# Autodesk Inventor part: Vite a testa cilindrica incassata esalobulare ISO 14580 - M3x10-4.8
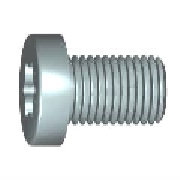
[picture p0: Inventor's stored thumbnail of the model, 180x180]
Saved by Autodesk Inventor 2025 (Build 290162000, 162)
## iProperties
Created: 2024-01
Part Number: Vite a testa cilindrica incassata esalobulare ISO 14580 - M3x10-4.8
Material: Acciaio
Description: ISO 14580 - Viti a testa cilindrica incassata esalobulare - Seconda edizione
Document SubType Name: Modeling
Standard: 14580
Designer: Ryzen5700u
Standards Organization: ISO
Language: it-IT
Size Designation: M3x10-4.8
Categories: <MemberInstance><Categories><Category DisplayName="Elementi di fissaggio" InternalName="e4da775c-781d-43d5-af7c-5136215cf5a6" Mnemonic="FSTN"><Category DisplayN
Density: 7.85 g/cm^3
Appearance: Lamiera
IsCustomPart: 0
Author: Ryzen5700u
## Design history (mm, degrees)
revolve "Revolution1" stored, may be unused: angle "d4" = 90 deg
thread "Thread1" dims "d6" = 10 (= b), "d7" = 0
sketch "Sketch2" dims "d21" = 2.8 (= A_)
  geometry: L1 (-0.849, -0.49)-(-1.4, 0); L2 (0, 0)-(-0.849, -0.49); L3 (0, 0)-(-0.849, 0.49); L4 (-4.144, 0)-(4.144, 0) reference; L5 (-1.4, 0)-(-0.849, 0.49); A1 r 0.98 centre (0, 0) between (-0.849, -0.49) and (-0.849, 0.49); 2 further points
  constraints: 8 end point, 2 coincident, 2 point on circle, 1 centre point, 1 horizontal alignment, 1 point on line, 2 other
  dimensions: "d19" = 60 deg angle of L3 L2; "d20" = 30 deg angle of L3 L4 (= 0.5 x d19); "d26" = 1.96 diameter of A1 (= 0.7 x d21)
extrude "Extrusion1" cut sketch "Sketch2" distance "d27" = 1.27 (= t); taper "d28" = 0 deg
pattern_circular "Circular Pattern1" dims angle "d30" = 360 deg
fillet "Fillet2" dims "d32" = 0.3 (= v)
fillet "Fillet3" dims "d33" = 0.3 (= v)
fillet "Fillet5" dims "d35" = 0.1 (= r)
chamfer "Chamfer2" distance "d36" = 0.3 (= v); stored, may be unused: second distance "d37" = 2, angle "d38" = 45 deg
body "Solid1"
sketch "Sketch1"
  geometry: L1 (0, 0)-(10, 0); L2 (10, 0)-(10, 1.5); L3 (10, 1.5)-(0, 1.5); L4 (0, 1.5)-(0, 0); L5 (0, 0)-(-2.4, 0); L6 (-2.4, 0)-(-2.4, 2.75); L7 (-2.4, 2.75)-(0, 2.96); L8 (0, 2.96)-(0, 0)
  constraints: 16 end point, 3 parallel, 2 horizontal, 2 perpendicular
  dimensions: "d0" = 3 diameter of L3 L1 (= d); "d3" = 10 distance of L2.end L3.end (= l_); "d46" = 85 deg angle of L8 L7; "d47" = 2.4 distance between parallel lines of L8 L6 (= k); "d49" = 5.5 diameter of L6.end L1 (= dk)
other parameters: "A_" = 2.8 [user parameter; used in 1 equation term], "d" = 3 [user parameter; used in 2 equation terms], "dk" = 5.5 [user parameter; used in 1 equation term], "k" = 2.4 [user parameter; used in 1 equation term], "l_" = 10 [user parameter; used in 2 equation terms], "lg" = 0 [user parameter; used in 1 equation term], "t" = 1.27 [user parameter; used in 1 equation term], "w" = 0.55 [user parameter], "v" = 0.3 [user parameter; used in 3 equation terms], "r" = 0.1 [user parameter; used in 1 equation term], "da" = 2.6 [user parameter], "ds_" = 3 (= d) [user parameter], "ls" = 0 [user parameter], "b" = 10 (= l_ - lg) [user parameter; used in 1 equation term], "d42" = 0, "d43" = 0, "d44" = 0, "p" = 0.5 [user parameter]
